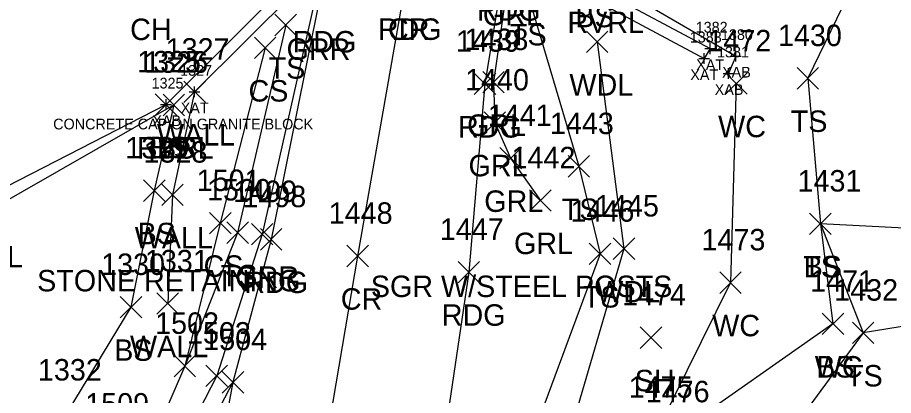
# Model space of a CAD drawing. Extents: x 1678553 to 1680768, y 787260 to 792325.
# Drawn here: x 1678655.8 to 1678737.4, y 787483.5 to 787518.8 of the extents above; entities that cross this region are included whole.
import ezdxf

# ---------------------------------------------------------------- set-up
doc = ezdxf.new("R2010")
doc.units = 0
for name, color, linetype in [('B_A', 7, 'Continuous'), ('B_C', 7, 'Continuous'), ('B_I', 7, 'Continuous'), ('B_TIC', 7, 'Continuous'), ('BSUBM', 7, 'Continuous'), ('L_A', 7, 'Continuous'), ('L_C', 7, 'Continuous'), ('L_I', 7, 'Continuous'), ('L_TIC', 7, 'Continuous'), ('LAWA', 7, 'Continuous'), ('LAWE', 7, 'Continuous'), ('LELB', 7, 'Continuous'), ('LW', 7, 'Continuous'), ('P_A', 7, 'Continuous'), ('P_I', 7, 'Continuous'), ('P_TIC', 7, 'Continuous'), ('PEU', 7, 'Continuous'), ('PRC', 7, 'Continuous'), ('R_A', 7, 'Continuous'), ('R_C', 7, 'Continuous'), ('R_I', 7, 'Continuous'), ('R_TIC', 7, 'Continuous'), ('RGR', 7, 'Continuous')]:
    doc.layers.add(name, color=color, linetype=linetype)

msp = doc.modelspace()

# ---------------------------------------------------------------- linework, layer by layer
at = {"layer": 'B_TIC'}
for p, q in [((1678720.311, 787515.858), (1678720.387, 787515.858)), ((1678719.759, 787514.931), (1678719.834, 787514.931)), ((1678719.759, 787514.931), (1678719.834, 787514.931)), ((1678722.705, 787515.164), (1678722.781, 787515.164)), ((1678722.013, 787513.547), (1678722.088, 787513.547)), ((1678672.288, 787511.834), (1678672.363, 787511.834)), ((1678669.625, 787510.644), (1678669.7, 787510.644))]:
    msp.add_line(p, q, dxfattribs=at)
for points in [[(1678720.308, 787515.358), (1678720.308, 787516.358)], [(1678719.755, 787514.431), (1678719.755, 787515.431)], [(1678719.755, 787514.431), (1678719.755, 787515.431)], [(1678719.808, 787515.858), (1678720.808, 787515.858)], [(1678722.702, 787514.664), (1678722.702, 787515.664)], [(1678719.255, 787514.931), (1678720.255, 787514.931)], [(1678719.255, 787514.931), (1678720.255, 787514.931)], [(1678722.202, 787515.164), (1678723.202, 787515.164)], [(1678722.009, 787513.047), (1678722.009, 787514.047)], [(1678721.509, 787513.547), (1678722.509, 787513.547)], [(1678672.284, 787511.334), (1678672.284, 787512.334)], [(1678671.784, 787511.834), (1678672.784, 787511.834)], [(1678669.121, 787510.644), (1678670.121, 787510.644)], [(1678669.621, 787510.144), (1678669.621, 787511.144)]]:
    msp.add_lwpolyline(points, dxfattribs=at)
at = {"layer": 'BSUBM'}
for points in [[(1678669.621, 787510.644), (1678682.749, 787523.742), (1678702.286, 787526.696), (1678709.309, 787522.854), (1678710.45, 787522.307), (1678722.702, 787515.164), (1678722.009, 787513.547)], [(1678703.192, 787523.813), (1678703.388, 787524.9), (1678720.308, 787515.858), (1678719.755, 787514.931)], [(1678703.192, 787523.813), (1678719.755, 787514.931)], [(1678681.717, 787521.255), (1678672.284, 787511.834)]]:
    msp.add_lwpolyline(points, dxfattribs=at)
at = {"layer": 'L_TIC'}
for points in [[(1678679.77, 787517.059), (1678681.77, 787519.059)], [(1678681.77, 787517.059), (1678679.77, 787519.059)], [(1678708.783, 787515.485), (1678710.783, 787517.485)], [(1678710.783, 787515.485), (1678708.783, 787517.485)], [(1678677.865, 787514.928), (1678679.865, 787516.928)], [(1678679.865, 787514.928), (1678677.865, 787516.928)], [(1678728.409, 787512.098), (1678730.409, 787514.098)], [(1678730.409, 787512.098), (1678728.409, 787514.098)], [(1678721.745, 787511.606), (1678723.745, 787513.606)], [(1678723.745, 787511.606), (1678721.745, 787513.606)], [(1678671.284, 787510.834), (1678673.284, 787512.834)], [(1678673.284, 787510.834), (1678671.284, 787512.834)], [(1678668.621, 787509.644), (1678670.621, 787511.644)], [(1678670.621, 787509.644), (1678668.621, 787511.644)], [(1678669.341, 787509.611), (1678671.341, 787511.611)], [(1678671.341, 787509.611), (1678669.341, 787511.611)], [(1678669.341, 787509.611), (1678671.341, 787511.611)], [(1678671.341, 787509.611), (1678669.341, 787511.611)], [(1678707.077, 787503.893), (1678709.077, 787505.893)], [(1678709.077, 787503.893), (1678707.077, 787505.893)], [(1678667.529, 787501.631), (1678669.529, 787503.631)], [(1678669.529, 787501.631), (1678667.529, 787503.631)], [(1678669.22, 787501.24), (1678671.22, 787503.24)], [(1678671.22, 787501.24), (1678669.22, 787503.24)], [(1678673.68, 787498.595), (1678675.68, 787500.595)], [(1678675.68, 787498.595), (1678673.68, 787500.595)], [(1678729.574, 787498.544), (1678731.574, 787500.544)], [(1678731.574, 787498.544), (1678729.574, 787500.544)], [(1678729.574, 787498.544), (1678731.574, 787500.544)], [(1678731.574, 787498.544), (1678729.574, 787500.544)], [(1678675.295, 787497.712), (1678677.295, 787499.712)], [(1678677.295, 787497.712), (1678675.295, 787499.712)], [(1678709.048, 787495.734), (1678711.048, 787497.734)], [(1678711.048, 787495.734), (1678709.048, 787497.734)], [(1678711.28, 787496.217), (1678713.28, 787498.217)], [(1678713.28, 787496.217), (1678711.28, 787498.217)], [(1678721.195, 787493.059), (1678723.195, 787495.059)], [(1678723.195, 787493.059), (1678721.195, 787495.059)], [(1678665.357, 787490.771), (1678667.357, 787492.771)], [(1678667.357, 787490.771), (1678665.357, 787492.771)], [(1678668.778, 787491.108), (1678670.778, 787493.108)], [(1678670.778, 787491.108), (1678668.778, 787493.108)], [(1678730.749, 787489.21), (1678732.749, 787491.21)], [(1678732.749, 787489.21), (1678730.749, 787491.21)], [(1678730.749, 787489.21), (1678732.749, 787491.21)], [(1678732.749, 787489.21), (1678730.749, 787491.21)], [(1678733.556, 787488.379), (1678735.556, 787490.379)], [(1678735.556, 787488.379), (1678733.556, 787490.379)], [(1678733.556, 787488.379), (1678735.556, 787490.379)], [(1678735.556, 787488.379), (1678733.556, 787490.379)], [(1678713.797, 787487.931), (1678715.797, 787489.931)], [(1678715.797, 787487.931), (1678713.797, 787489.931)], [(1678670.376, 787485.283), (1678672.376, 787487.283)], [(1678672.376, 787485.283), (1678670.376, 787487.283)], [(1678670.376, 787485.283), (1678672.376, 787487.283)], [(1678672.376, 787485.283), (1678670.376, 787487.283)], [(1678674.858, 787483.768), (1678676.858, 787485.768)], [(1678676.858, 787483.768), (1678674.858, 787485.768)]]:
    msp.add_lwpolyline(points, dxfattribs=at)
at = {"layer": 'LAWA'}
msp.add_lwpolyline([(1678709.783, 787516.485), (1678712.28, 787497.217), (1678701.786, 787461.308), (1678703.147, 787457.419), (1678705.06, 787457.531), (1678706.335, 787458.183), (1678713.921, 787445.734), (1678717.921, 787439.613), (1678723.5, 787424.177), (1678713.912, 787402.698), (1678707.751, 787397.775), (1678697.862, 787399.447), (1678688.053, 787395.99), (1678683.78, 787387.208), (1678676.741, 787361.633), (1678672.526, 787349.762), (1678668.76, 787338.441), (1678662.119, 787319.948), (1678654.202, 787273.362)], dxfattribs=at)
at = {"layer": 'LAWE'}
for points in [[(1678722.745, 787512.606), (1678722.195, 787494.059), (1678715.409, 787480.322), (1678713.685, 787473.198), (1678709.183, 787469.54), (1678703.147, 787457.419), (1678711.034, 787444.117)], [(1678597.83, 787442.87), (1678613.996, 787449.694), (1678631.371, 787455.115), (1678641.597, 787473.632), (1678648.099, 787489.375), (1678652.594, 787500.479), (1678670.341, 787510.611)], [(1678731.749, 787490.21), (1678717.048, 787479.906), (1678716.12, 787473.35), (1678711.115, 787467.484), (1678705.06, 787457.531), (1678712.259, 787444.43), (1678711.034, 787444.117)]]:
    msp.add_lwpolyline(points, dxfattribs=at)
at = {"layer": 'LELB'}
for points in [[(1678740.071, 787535.07), (1678729.409, 787513.098), (1678730.574, 787499.544), (1678734.556, 787489.379)], [(1678812.504, 787523.781), (1678787.366, 787520.276), (1678755.257, 787498.254), (1678730.574, 787499.544), (1678731.749, 787490.21)], [(1678703.248, 787521.158), (1678708.077, 787504.893), (1678710.048, 787496.734), (1678699.74, 787468.921), (1678698.818, 787457.487), (1678706.749, 787433.933), (1678714.451, 787417.51), (1678705.647, 787404.222), (1678696.305, 787404.911), (1678687.529, 787400.609), (1678678.856, 787394.601), (1678669.013, 787365.188), (1678664.736, 787349.076), (1678657.46, 787321.279), (1678652.337, 787297.827), (1678647.466, 787276.322)], [(1678680.77, 787518.059), (1678676.295, 787498.712), (1678671.376, 787486.283), (1678667.842, 787478.106), (1678658.92, 787472.197), (1678652.163, 787452.167), (1678649.267, 787436.424), (1678649.323, 787416.121), (1678648.829, 787401.973), (1678646.777, 787382.688), (1678641.038, 787357.729), (1678634.181, 787333.529), (1678626.232, 787302.071), (1678622.908, 787282.585)], [(1678812.782, 787516.249), (1678783.274, 787510.424), (1678763.1, 787494.005), (1678734.556, 787489.379), (1678724.288, 787475.377)], [(1678678.865, 787515.928), (1678674.68, 787499.595), (1678671.376, 787486.283)], [(1678597.927, 787443.886), (1678613.143, 787451.796), (1678631.307, 787457.627), (1678640.506, 787474.592), (1678646.468, 787489.445), (1678651.341, 787501.275), (1678669.621, 787510.644)], [(1678670.341, 787510.611), (1678668.529, 787502.631), (1678666.357, 787491.771), (1678660.381, 787481.936), (1678643.296, 787471.259), (1678637.927, 787460.78), (1678638.178, 787442.595), (1678641.032, 787418.209), (1678640.004, 787400.912), (1678637.638, 787392.163), (1678640.142, 787385.556), (1678638.302, 787358.255), (1678630.002, 787335.833)], [(1678675.858, 787484.768), (1678671.596, 787476.604), (1678669.159, 787477.034), (1678667.842, 787478.106)]]:
    msp.add_lwpolyline(points, dxfattribs=at)
at = {"layer": 'LW'}
msp.add_lwpolyline([(1678672.284, 787511.834), (1678670.22, 787502.24), (1678669.778, 787492.108)], dxfattribs=at)
at = {"layer": 'P_TIC'}
for points in [[(1678698.331, 787511.572), (1678700.331, 787513.572)], [(1678700.331, 787511.572), (1678698.331, 787513.572)], [(1678678.423, 787497.085), (1678680.423, 787499.085)], [(1678680.423, 787497.085), (1678678.423, 787499.085)], [(1678686.471, 787495.537), (1678688.471, 787497.537)], [(1678688.471, 787495.537), (1678686.471, 787497.537)], [(1678696.82, 787494.037), (1678698.82, 787496.037)], [(1678698.82, 787494.037), (1678696.82, 787496.037)], [(1678674.858, 787483.768), (1678676.858, 787485.768)], [(1678676.858, 787483.768), (1678674.858, 787485.768)]]:
    msp.add_lwpolyline(points, dxfattribs=at)
at = {"layer": 'PEU'}
for points in [[(1678701.084, 787523.46), (1678691.863, 787521.675), (1678683.928, 787520.501), (1678679.423, 787498.085), (1678675.858, 787484.768), (1678672.353, 787466.03), (1678666.651, 787446.983), (1678662.975, 787430.653), (1678658.139, 787412.595), (1678657.115, 787400.242), (1678651.997, 787380.889), (1678646.796, 787355.993), (1678640.868, 787332.433), (1678631.508, 787300.964), (1678626.743, 787281.591)], [(1678701.084, 787523.46), (1678699.331, 787512.572), (1678697.82, 787495.037), (1678694.118, 787469.827), (1678689.971, 787450.935), (1678685.799, 787426.952), (1678675.551, 787395.19), (1678665.556, 787365.837), (1678662.398, 787349.046), (1678655.839, 787321.611), (1678650.229, 787298.04), (1678645.331, 787276.771)]]:
    msp.add_lwpolyline(points, dxfattribs=at)
at = {"layer": 'PRC'}
msp.add_lwpolyline([(1678691.863, 787521.675), (1678687.471, 787496.537), (1678683.409, 787472.735), (1678673.582, 787430.342), (1678667.066, 787403.394), (1678661.63, 787379.176), (1678654.8, 787353.827), (1678646.933, 787323.808), (1678641.795, 787300.306), (1678636.187, 787278.722)], dxfattribs=at)
at = {"layer": 'R_TIC'}
for points in [[(1678699.119, 787511.729), (1678701.119, 787513.729)], [(1678701.119, 787511.729), (1678699.119, 787513.729)], [(1678699.258, 787507.965), (1678701.258, 787509.965)], [(1678701.258, 787507.965), (1678699.258, 787509.965)], [(1678700.723, 787504.648), (1678702.723, 787506.648)], [(1678702.723, 787504.648), (1678700.723, 787506.648)], [(1678703.495, 787500.711), (1678705.495, 787502.711)], [(1678705.495, 787500.711), (1678703.495, 787502.711)], [(1678677.582, 787497.569), (1678679.582, 787499.569)], [(1678679.582, 787497.569), (1678677.582, 787499.569)], [(1678673.343, 787484.377), (1678675.343, 787486.377)], [(1678675.343, 787484.377), (1678673.343, 787486.377)]]:
    msp.add_lwpolyline(points, dxfattribs=at)
at = {"layer": 'RGR'}
for points in [[(1678701.594, 787523.02), (1678700.119, 787512.729), (1678700.258, 787508.965), (1678701.723, 787505.648), (1678704.495, 787501.711)], [(1678683.363, 787519.815), (1678678.582, 787498.569), (1678674.343, 787485.377), (1678670.471, 787477.811)]]:
    msp.add_lwpolyline(points, dxfattribs=at)

# ---------------------------------------------------------------- texts
at = {"layer": 'B_A'}
for s, p in [('XAT', (1678719.012, 787513.858)), ('XAT', (1678718.46, 787512.931)), ('XAT', (1678718.46, 787512.931)), ('XAB', (1678721.422, 787513.164)), ('XAB', (1678720.73, 787511.547)), ('XAT', (1678670.989, 787509.834)), ('XAB', (1678668.342, 787508.644))]:
    msp.add_text(s, height=1, dxfattribs=at).set_placement(p)
at = {"layer": 'B_C'}
msp.add_text('CONCRETE CAP ON GRANITE BLOCK', height=1, dxfattribs=at).set_placement((1678659.111, 787508.334))
at = {"layer": 'B_I'}
for s, p in [('1382', (1678718.961, 787517.358)), ('1383', (1678718.409, 787516.431)), ('1383', (1678718.409, 787516.431)), ('1380', (1678721.312, 787516.664)), ('1381', (1678720.946, 787515.047)), ('1327', (1678670.938, 787513.334)), ('1325', (1678668.275, 787512.144))]:
    msp.add_text(s, height=1, dxfattribs=at).set_placement(p)
at = {"layer": 'L_A'}
for s, p in [('BS', (1678707.75, 787517.854)), ('CH', (1678666.28, 787516.658)), ('RVRL', (1678707.017, 787517.307)), ('TS', (1678701.658, 787516.158)), ('TS', (1678679.18, 787513.059)), ('CS', (1678677.306, 787510.928)), ('WDL', (1678707.2, 787511.485)), ('TS', (1678727.818, 787508.098)), ('WC', (1678721.052, 787507.606)), ('WALL', (1678668.772, 787506.834)), ('RVRL', (1678666.908, 787505.611)), ('BS', (1678668.062, 787505.644)), ('BS', (1678668.782, 787505.611)), ('TS', (1678706.486, 787499.893)), ('WALL', (1678666.709, 787497.24)), ('BS', (1678666.97, 787497.631)), ('RVRL', (1678649.161, 787495.479)), ('CS', (1678673.121, 787494.595)), ('TS', (1678728.984, 787494.544)), ('BS', (1678729.015, 787494.544)), ('TS', (1678674.705, 787493.712)), ('WDL', (1678709.697, 787492.217)), ('TS', (1678708.458, 787491.734)), ('WC', (1678720.502, 787489.059)), ('BS', (1678664.798, 787486.771)), ('WALL', (1678666.266, 787487.108)), ('WC', (1678730.056, 787485.21)), ('BS', (1678730.189, 787485.21)), ('TS', (1678732.966, 787484.379)), ('TS', (1678732.966, 787484.379)), ('SH', (1678713.285, 787483.931))]:
    msp.add_text(s, height=2, dxfattribs=at).set_placement(p)
at = {"layer": 'L_C'}
msp.add_text('STONE RETAINING', height=2, dxfattribs=at).set_placement((1678657.615, 787493.24))
at = {"layer": 'L_I'}
for s, p in [('1430', (1678726.63, 787516.098)), ('1472', (1678720.052, 787515.606)), ('1327', (1678669.591, 787514.834)), ('1325', (1678666.929, 787513.644)), ('1326', (1678667.593, 787513.611)), ('1326', (1678667.593, 787513.611)), ('1443', (1678705.384, 787507.893)), ('1329', (1678665.828, 787505.631)), ('1328', (1678667.528, 787505.24)), ('1501', (1678672.476, 787502.595)), ('1431', (1678728.449, 787502.544)), ('1431', (1678728.449, 787502.544)), ('1500', (1678673.437, 787501.712)), ('1446', (1678707.3, 787499.734)), ('1445', (1678709.587, 787500.217)), ('1473', (1678719.502, 787497.059)), ('1330', (1678663.577, 787494.771)), ('1331', (1678667.652, 787495.108)), ('1471', (1678729.623, 787493.21)), ('1471', (1678729.623, 787493.21)), ('1432', (1678731.864, 787492.379)), ('1432', (1678731.864, 787492.379)), ('1474', (1678712.104, 787491.931)), ('1502', (1678668.605, 787489.283)), ('1502', (1678668.605, 787489.283)), ('1504', (1678673.086, 787487.768)), ('1332', (1678657.689, 787484.936)), ('1475', (1678712.717, 787483.322)), ('1476', (1678714.301, 787482.906)), ('1509', (1678662.095, 787481.76))]:
    msp.add_text(s, height=2, dxfattribs=at).set_placement(p)
at = {"layer": 'P_A'}
for s, p in [('RDG', (1678698.572, 787518.46)), ('RDG', (1678698.572, 787518.46)), ('RDG', (1678689.351, 787516.675)), ('CR', (1678690.296, 787516.675)), ('RDG', (1678681.416, 787515.501)), ('RDG', (1678696.819, 787507.572)), ('RDG', (1678676.911, 787493.085)), ('CR', (1678685.904, 787491.537)), ('RDG', (1678695.308, 787490.037))]:
    msp.add_text(s, height=2, dxfattribs=at).set_placement(p)
at = {"layer": 'P_I'}
for s, p in [('1439', (1678696.631, 787515.572)), ('1498', (1678676.731, 787501.085)), ('1448', (1678684.778, 787499.537)), ('1447', (1678695.127, 787498.037)), ('1504', (1678673.086, 787487.768))]:
    msp.add_text(s, height=2, dxfattribs=at).set_placement(p)
at = {"layer": 'R_A'}
for s, p in [('GRL', (1678699.137, 787518.02)), ('GRR', (1678680.851, 787514.815)), ('GRL', (1678697.662, 787507.729)), ('GRL', (1678697.801, 787503.965)), ('GRL', (1678699.266, 787500.648)), ('GRL', (1678702.038, 787496.711)), ('GRR', (1678676.07, 787493.569))]:
    msp.add_text(s, height=2, dxfattribs=at).set_placement(p)
at = {"layer": 'R_C'}
msp.add_text('SGR W/STEEL POSTS', height=2, dxfattribs=at).set_placement((1678688.7, 787492.711))
at = {"layer": 'R_I'}
for s, p in [('1438', (1678697.426, 787515.729)), ('1440', (1678697.479, 787511.965)), ('1441', (1678699.597, 787508.648)), ('1442', (1678701.802, 787504.711)), ('1499', (1678675.882, 787501.569)), ('1503', (1678671.572, 787488.377))]:
    msp.add_text(s, height=2, dxfattribs=at).set_placement(p)

doc.saveas('drawing.dxf')
